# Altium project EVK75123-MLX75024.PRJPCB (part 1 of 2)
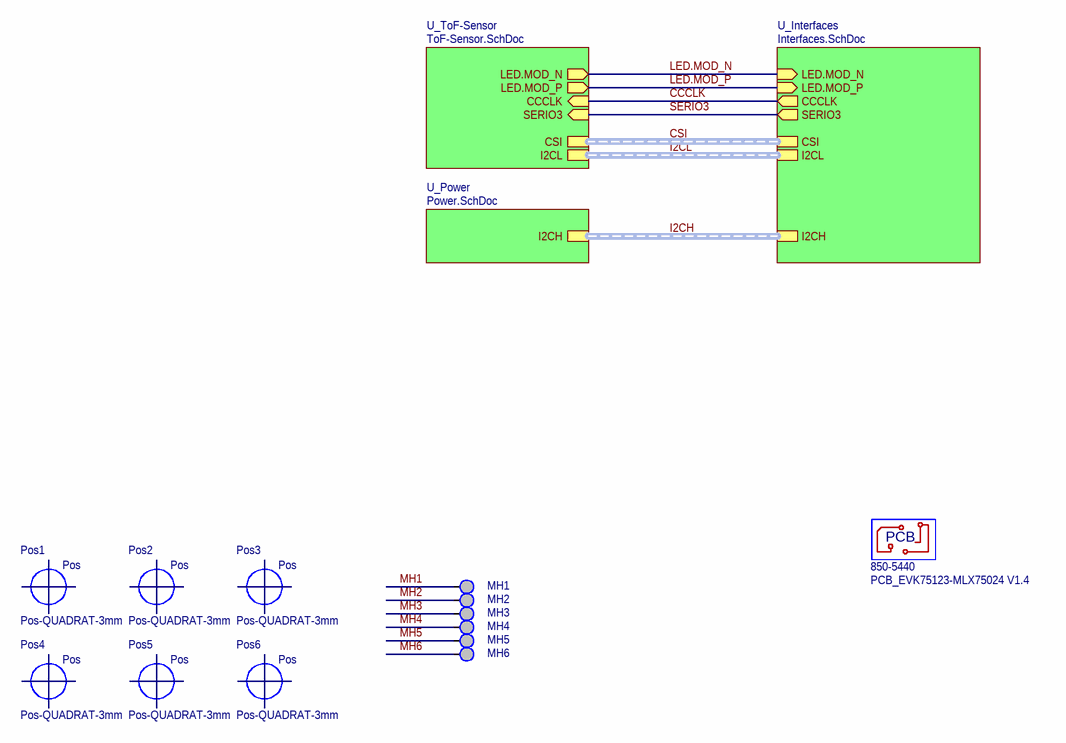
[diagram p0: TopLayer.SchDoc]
prj_vers: V1.4; prj_num: PN2017002.13; prj_name: EVK75123-MLX75024
4 sheets, 222 parts. Net scope: hierarchical (ports join the sheet entries above them; power ports are global).
Board file: EVK75123-MLX75024.PcbDoc
Sheets:
  TopLayer.SchDoc
    U_Power = Power.SchDoc
    U_ToF-Sensor = ToF-Sensor.SchDoc
    U_Interfaces = Interfaces.SchDoc

## Sheet TopLayer.SchDoc: Top Layer
size A4; CheckedBy: ROB; Author: Vorname Nachname; DrawnBy: DST; Organization: BECOM BLUETECHNIX; Address1: Gutheil-Schoder-Gasse 17; Address2: A - 1230 Wien; Address3: AUSTRIA; DocumentNumber: 1; Revision: V1.0; SheetNumber: 1; SheetTotal: 4; PageSetup: Record=PageOptions¦CenterHorizontal=True¦CenterVertical=True¦PrintScale=1.00¦XCorrection=1.00¦YCorrection=1.00¦PrintKind=0¦BorderSize=5000000¦LeftOffset=0¦BottomOffset=0¦Orientation=2¦PaperLength=1000¦PaperWidth=1000¦Scale=100¦PaperSource=15¦PrintQuality=600¦MediaType=1¦DitherType=10¦PrintScaleMode=1¦PaperKind=A4 (210 x 297 mm)

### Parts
MH1  Test Pad  [PAD_M2-5x5]  (value not drawn)  (no BOM)
MH2  Test Pad  [PAD_M2-5x5]  (value not drawn)  (no BOM)
MH3  Test Pad  [PAD_M2-5x5]  (value not drawn)  (no BOM)
MH4  Test Pad  [PAD_M2-5x5]  (value not drawn)  (no BOM)
MH5  Test Pad  [PAD_M2-5x5]  (value not drawn)  (no BOM)
MH6  Test Pad  [PAD_M2-5x5]  (value not drawn)  (no BOM)
PCB  850-5440  [PCB]
Pos1  Position  [Pos-QUADRAT]  (value not drawn)
Pos2  Position  [Pos-QUADRAT]  (value not drawn)
Pos3  Position  [Pos-QUADRAT]  (value not drawn)
Pos4  Position  [Pos-QUADRAT]  (value not drawn)
Pos5  Position  [Pos-QUADRAT]  (value not drawn)
Pos6  Position  [Pos-QUADRAT]  (value not drawn)

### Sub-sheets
U_Interfaces = Interfaces.SchDoc: I2CL (harness I2C), CCCLK (out), LED.MOD_N (in), LED.MOD_P (in), CSI (harness CSI), I2CH (harness I2C), SERIO3 (out)
U_Power = Power.SchDoc: I2CH (harness I2C)
U_ToF-Sensor = ToF-Sensor.SchDoc: LED.MOD_N (out), LED.MOD_P (out), CSI (harness CSI), CCCLK (in), I2CL (harness I2C), SERIO3 (in)

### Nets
CCCLK: sheet U_ToF-Sensor/CCCLK, sheet U_Interfaces/CCCLK
LED.MOD_N: sheet U_ToF-Sensor/LED.MOD_N, sheet U_Interfaces/LED.MOD_N
LED.MOD_P: sheet U_ToF-Sensor/LED.MOD_P, sheet U_Interfaces/LED.MOD_P
MH1: MH1.1
MH2: MH2.1
MH3: MH3.1
MH4: MH4.1
MH5: MH5.1
MH6: MH6.1
SERIO3: sheet U_ToF-Sensor/SERIO3, sheet U_Interfaces/SERIO3

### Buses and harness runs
harness CSI = sheet U_Interfaces/CSI = sheet U_ToF-Sensor/CSI
harness I2CH = sheet U_Interfaces/I2CH = sheet U_Power/I2CH
harness I2CL = sheet U_Interfaces/I2CL = sheet U_ToF-Sensor/I2CL

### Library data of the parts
MH1-MH6 = d95d2f47-965b-47b2-ac00-e8d5b9325de3: M2 Mounting Hole 5x5; Manufacturer: Bluetechnix; ArticleNumber: 810-0545; Inventory Storage Name: L2; Sachgruppe: SV_TEST; IsReviewed: 1; Typ: Mount Hole
PCB = aa2248c4-82a7-44fd-bdc5-6c4486715852: PCB_EVK75123-MLX75024 V1.4; Manufacturer: Bluetechnix; Inventory Storage Name: L2; Sachgruppe: PCB_EXTPROJEKT; SachgruppeCode: externe Projekte; IsReviewed: 0; Kunde: Melexis
Pos1-Pos6 = A97550DC-E5EA-465D-9168-34E3565B8720: Pos-QUADRAT-3mm; Manufacturer: Bluetechnix; MountOption: DNP; ArticleNumber: 880-0007; Inventory Storage Name: L2; Sachgruppe: DIV_SYMBOLE; SachgruppeCode: PCB-Symbole; IsReviewed: 1; Groesse: 3mm

## Sheet Power.SchDoc: Power Supplies
size A4; CheckedBy: ROB; Author: Vorname Nachname; DrawnBy: DST; Organization: BECOM BLUETECHNIX; Address1: Gutheil-Schoder-Gasse 17; Address2: A - 1230 Wien; Address3: AUSTRIA; DocumentNumber: 4; Revision: V1.0; SheetNumber: 4; SheetTotal: 4
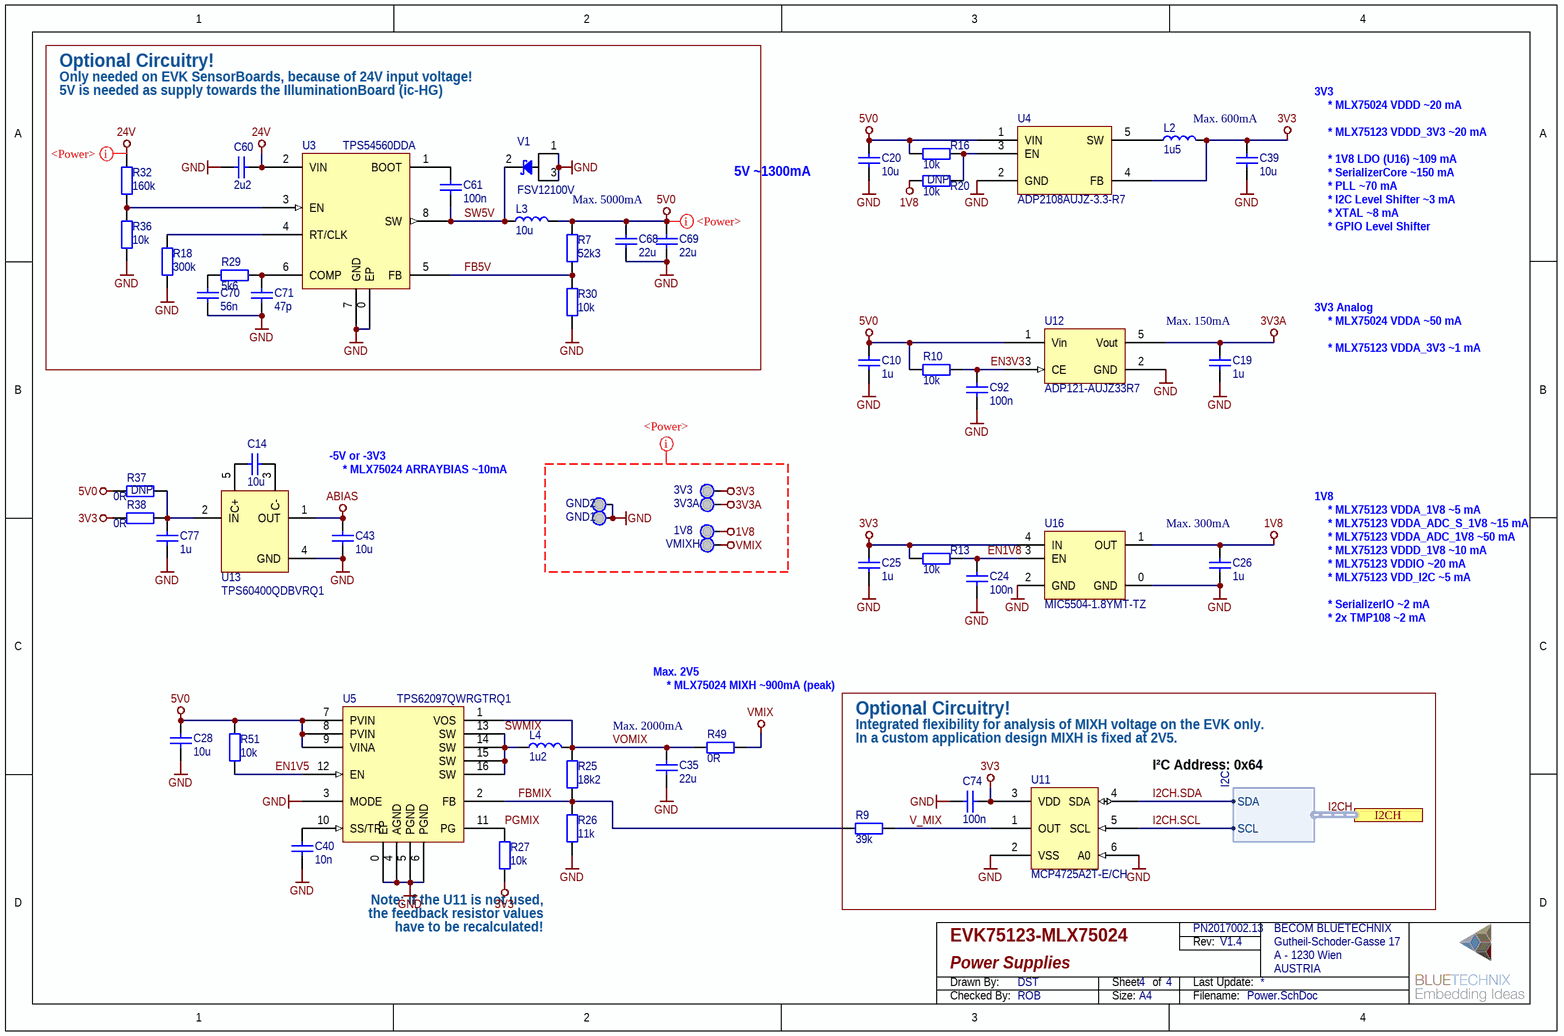
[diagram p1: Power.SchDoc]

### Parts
1V8  Test Pad  [PAD_1.27mm_HMD]  (value not drawn)  (no BOM)
3V3  Test Pad  [PAD_1.27mm_HMD]  (value not drawn)  (no BOM)
3V3A  Test Pad  [PAD_1.27mm_HMD]  (value not drawn)  (no BOM)
C10  C: 1u  [0805]  (hidden comment: Capacitor non-polarized)
C14  C: 10u  [0805]  (hidden comment: Capacitor non-polarized)
C19  C: 1u  [0805]  (hidden comment: Capacitor non-polarized)
C20  C: 10u  [0805]  (hidden comment: Capacitor non-polarized)
C24  C: 100n  [0402]  (hidden comment: Capacitor non-polarized)
C25  C: 1u  [0805]  (hidden comment: Capacitor non-polarized)
C26  C: 1u  [0805]  (hidden comment: Capacitor non-polarized)
C28  C: 10u  [0805]  (hidden comment: Capacitor non-polarized)
C35  C: 22u  [1206]  (hidden comment: Capacitor non-polarized)
C39  C: 10u  [0805]  (hidden comment: Capacitor non-polarized)
C40  C: 10n  [0402]  (hidden comment: Capacitor non-polarized)
C43  C: 10u  [0805]  (hidden comment: Capacitor non-polarized)
C60  C: 2u2  [1210]  (hidden comment: Capacitor non-polarized)
C61  C: 100n  [0402]  (hidden comment: Capacitor non-polarized)
C68  C: 22u  [1206]  (hidden comment: Capacitor non-polarized)
C69  C: 22u  [1206]  (hidden comment: Capacitor non-polarized)
C70  C: 56n  [0402]  (hidden comment: Capacitor non-polarized)
C71  C: 47p  [0402]  (hidden comment: Capacitor non-polarized)
C74  C: 100n  [0402]  (hidden comment: Capacitor non-polarized)
C77  C: 1u  [0805]  (hidden comment: Capacitor non-polarized)
C92  C: 100n  [0402]  (hidden comment: Capacitor non-polarized)
GND1  Test Pad  [PAD_1.27mm_HMD]  (value not drawn)  (no BOM)
GND2  Test Pad  [PAD_1.27mm_HMD]  (value not drawn)  (no BOM)
L2  L: 1u5  [WE-TPC_S]  (hidden comment: Inductor)
L3  L: 10u  [CC-XAL5050]  (hidden comment: Inductor)
L4  L: 1u2  [WE-TPC_MH]  (hidden comment: Inductor)
R7  R: 52k3  [0402]  (hidden comment: Resistor)
R9  R: 39k  [0402]  (hidden comment: Resistor)
R10  R: 10k  [0402]  (hidden comment: Resistor)
R13  R: 10k  [0402]  (hidden comment: Resistor)
R16  R: 10k  [0402]  (hidden comment: Resistor)
R18  R: 300k  [0402]  (hidden comment: Resistor)
R20  R: 10k  MountOption: DNP  [0402]  (hidden comment: Resistor)
R25  R: 18k2  [0402]  (hidden comment: Resistor)
R26  R: 11k  [0402]  (hidden comment: Resistor)
R27  R: 10k  [0402]  (hidden comment: Resistor)
R29  R: 5k6  [0402]  (hidden comment: Resistor)
R30  R: 10k  [0402]  (hidden comment: Resistor)
R32  R: 160k  [0402]  (hidden comment: Resistor)
R36  R: 10k  [0402]  (hidden comment: Resistor)
R37  R: 0R  MountOption: DNP  [0805]  (hidden comment: Resistor)
R38  R: 0R  [0805]  (hidden comment: Resistor)
R49  R: 0R  [0805]  (hidden comment: Resistor)
R51  R: 10k  [0402]  (hidden comment: Resistor)
U3  NAME: TPS54560DDA  [PSO8-1.27-7.3]  (hidden comment: TPS54061)
U4  NAME: ADP2108AUJZ-3.3-R7  [TSOT23-5-0.95-2.8]  (hidden comment: ADP2108TSOP)
U5  NAME: TPS62097QWRGTRQ1  [VQFN16A4-0.5-3-1]  (hidden comment: TPS62097)
U11  NAME: MCP4725A2T-E/CH  [SOT23-6-0.95--3.3]  (hidden comment: MCP4725)
U12  NAME: ADP121-AUJZ33R7  [SOT23-5-0.95--3.6]  (hidden comment: High-Speed LDO Voltage-Regulator)
U13  NAME: TPS60400QDBVRQ1  [SOT23-5-0.95--3.6]  (hidden comment: MAX828)
U16  NAME: MIC5504-1.8YMT-TZ  [DFN4-0.65-1-0.5]  (hidden comment: MIC550x)
V1  NAME: FSV12100V  [TO-277-3]  (hidden comment: Default Diode)
VMIXH  Test Pad  [PAD_1.27mm_HMD]  (value not drawn)  (no BOM)

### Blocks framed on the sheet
Optional Circuitry!: C60 C61 C68-C71 L3 R7 R18 R29 R30 R32 R36 U3 V1
Optional Circuitry!: C74 R9 U11

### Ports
I2CH (harness I2C)

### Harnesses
I2C: SCL, SDA

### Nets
1V8: 1V8.1 C26.2 R20.1 U16.1(OUT)
3V3: 3V3.1 C25.2 C39.2 C74.2 L2.2 R13.1 R27.2 R38.2 U4.4(FB) U11.3(VDD) U16.4(IN)
3V3A: 3V3A.1 C19.2 U12.5(Vout)
5V0: C10.2 C20.2 C28.2 C68.2 C69.2 L3.2 R7.2 R10.1 R16.1 R37.2 R51.2 U4.1(VIN) U5.7(PVIN) U5.8(PVIN) U5.9(VINA) U12.1(Vin)
24V: C60.2 R32.2 U3.2(VIN)
ABIAS: C43.1 U13.1(OUT)
GND: C10.1 C19.1 C20.1 C24.2 C25.1 C26.1 C28.1 C35.1 C39.1 C40.1 C43.2 C60.1 C68.1 C69.1 C70.1 C71.1 C74.1 C77.1 C92.2 GND1.1 GND2.1 R18.1 R26.1 R30.2 R36.2 U3.0(EP) U3.7(GND) U4.2(GND) U5.0(EP) U5.3(MODE) U5.4(AGND) U5.5(PGND) U5.6(PGND) U11.2(VSS) U11.6(A0) U12.2(GND) U13.4(GND) U16.0(GND) U16.2(GND) V1.1(A) V1.3(A)
VMIX: R49.1 VMIXH.1
EN1V5: R51.1 U5.12(EN)
EN1V8: C24.1 R13.2 U16.3(EN)
EN3V3: C92.1 R10.2 U12.3(CE)
FB5V: R7.1 R30.1 U3.5(FB)
FBMIX: R9.1 R25.1 R26.2 U5.2(FB)
I2CH.SCL: U11.5(SCL) ; port I2CH.SCL
I2CH.SDA: U11.4(SDA) ; port I2CH.SDA
PGMIX: R27.1 U5.11(PG)
SW5V: C61.2 L3.1 U3.8(SW) V1.2(K)
SWMIX: L4.1 U5.13(SW) U5.14(SW) U5.15(SW) U5.16(SW)
V_MIX: R9.2 U11.1(OUT)
VOMIX: C35.2 L4.2 R25.2 R49.2 U5.1(VOS)
NetC14_1: C14.1 U13.3(C-)
NetC14_2: C14.2 U13.5(C+)
NetC40_2: C40.2 U5.10(SS/TR)
NetC61_1: C61.1 U3.1(BOOT)
NetC70_2: C70.2 R29.2
NetC71_2: C71.2 R29.1 U3.6(COMP)
NetC77_2: C77.2 R37.1 R38.1 U13.2(IN)
NetL2_1: L2.1 U4.5(SW)
NetR16_2: R16.2 R20.2 U4.3(EN)
NetR18_2: R18.2 U3.4(RT/CLK)
NetR32_1: R32.1 R36.1 U3.3(EN)

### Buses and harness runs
harness I2CH = port I2CH

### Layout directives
net class <Power>: 1V8, 3V3, 3V3A, 5V0, 24V, GND, VMIX

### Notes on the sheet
- Only needed on EVK SensorBoards, because of 24V input voltage!
- 5V is needed as supply towards the IlluminationBoard (ic-HG)
- 3V3
- * MLX75024 VDDD |0 mA
- 5V
  300mA
- (near L2) Max. 600mA
- * 1V8 LDO (U16)
  09 mA
- * MLX75123 VDDD_3V3 |0 mA
- * SerializerCore
  50 mA
- Max. 5000mA
- * PLL ~70 mA
- * I2C Level Shifter ~3 mA
- * XTAL ~8 mA
- * GPIO Level Shifter
- 3V3 Analog
- Max. 150mA
- * MLX75024 VDDA ~50 mA
- * MLX75123 VDDA_3V3
  mA
- -5V or -3V3
- * MLX75024 ARRAYBIAS
  0mA
- 1V8
- * MLX75123 VDDA_1V8 ~5 mA
- Max. 300mA
- * MLX75123 VDDA_ADC_S_1V8
  5 mA
- * MLX75123 VDDA_ADC_1V8 ~50 mA
- * MLX75123 VDDD_1V8
  0 mA
- * MLX75123 VDDIO |0 mA
- * MLX75123 VDD_I2C ~5 mA
- * SerializerIO | mA
- * 2x TMP108 | mA
- Max. 2V5
- * MLX75024 MIXH ~900mA (peak)
- Max. 2000mA
- Integrated flexibility for analysis of MIXH voltage on the EVK only.
- In a custom application design MIXH is fixed at 2V5.
- (near U11) I²C Address: 0x64
- Note: If the U11 is not used,
- the feedback resistor values
- have to be recalculated!

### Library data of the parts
1V8 3V3 3V3A GND1 GND2 VMIXH = 27F6ED3A-68E1-4461-ACCB-196987D0D511: Test Pad 1.27mm; Manufacturer: Bluetechnix; ArticleNumber: 810-0043; Inventory Storage Name: L2; Sachgruppe: SV_TEST; IsReviewed: 1
C10 C19 C25 C26 C77 = 81c3c59d-90b6-45b0-bf00-0272af6cd427: C-0805-1u-16V-10%; Manufacturer: KEMET; ArticleNumber: 710-0292; NAME: C0805C105K4RACTU; Inventory Storage Name: LBaut; Inventory Storage Section: C6; Sachgruppe: C_KERAMIK; SachgruppeCode: Keramikscheiben; IsReviewed: 1; InternalPrice: 0,037954; InternalStock: 308; U: 16V; Toleranz: 10%; Dielektrikum: X7R; T_Koeffizient: ±10%; T-bereich: -55°C : +125°C; Montage: SMD
C14 C20 C28 C39 C43 = cf916b3d-c256-4339-9e5e-93049cd4a086: C-0805-10u-6.3V-10%; Manufacturer: AVX; ArticleNumber: 710-0369; NAME: 08056C106KAT2A; Inventory Storage Name: LBaut; Sachgruppe: C_KERAMIK; SachgruppeCode: Keramikscheiben; IsReviewed: 1; InternalPrice: 0,227407; InternalStock: 48; U: 6.3V; Toleranz: 10%; Dielektrikum: X7R; T_Koeffizient: ±15%; T-bereich: -55°C : +125°C; Montage: SMD; Inventory Storage Section: C7
C24 C92 = 54C877D5-E705-4C14-AD3D-8F4F7B57D597: C-0402-100n-16V-10%; Manufacturer: Murata; ArticleNumber: 710-0138; NAME: GRM155R71C104KA88D; Inventory Storage Name: LBaut; Inventory Storage Section: C3; Sachgruppe: C_KERAMIK; SachgruppeCode: Keramikscheiben; IsReviewed: 1; U: 16V; Toleranz: 10%; Dielektrikum: X7R; T_Koeffizient: ± 15%; T-bereich: -55°C : +125°C; Montage: SMD; InternalPrice: 0.011327; InternalStock: 597514
C35 C68 C69 = f3686e78-9391-4e70-aeac-48820653bfbe: C-1206-22u-16V-10%-X6S; Manufacturer: Murata; ArticleNumber: 710-0343; NAME: GRM31CC81C226ME15L; Inventory Storage Name: LBaut; Sachgruppe: C_KERAMIK; SachgruppeCode: Keramikscheiben; IsReviewed: 1; InternalPrice: 0,277045; InternalStock: 60; U: 16V; Toleranz: 20%; Dielektrikum: X6S; T_Koeffizient: ± 15%; T-bereich: -55°C : +105°C; Montage: SMD; Inventory Storage Section: C7
C40 = F3AE35C4-38BD-40F1-9F89-DFB06C81C85C: C-0402-10n-25V-10%; Manufacturer: Murata; ArticleNumber: 710-0222; NAME: GRM155R71E103KA01D; Inventory Storage Name: LBaut; Inventory Storage Section: C5; Sachgruppe: C_KERAMIK; SachgruppeCode: Keramikscheiben; IsReviewed: 1; InternalPrice: 0,008319; InternalStock: 2134; U: 25V; Toleranz: 10%; Dielektrikum: X7R; T_Koeffizient: ± 15%; T-bereich: -55°C : +125°C; Montage: SMD
C60 = c11633e3-883f-4ea1-bab5-305a930c1712: C-1210-2u2-100V-X7R; Manufacturer: Kemet; ArticleNumber: 710-0311; NAME: C1210C225K1RACTU; Inventory Storage Name: LBaut; Inventory Storage Section: C6; Sachgruppe: C_KERAMIK; SachgruppeCode: Keramikscheiben; IsReviewed: 1; InternalPrice: 0,222241; U: 100V; Toleranz: 10%; Dielektrikum: X7R; T_Koeffizient: ± 15%; T-bereich: -55°C : +125°C; Montage: SMD; InternalStock: 196
C61 = 54C877D5-E705-4C14-AD3D-8F4F7B57D597: C-0402-100n-16V-10%; manufacturer: Murata; ArticleNumber: 710-0138; Inventory Storage Name: LBaut; Inventory Storage Section: C3; IsReviewed: 1; NAME: GRM155R71C104KA88D; Sachgruppe: C_KERAMIK; SachgruppeCode: Keramikscheiben; Dielektrikum: X7R; Montage: SMD; T-bereich: -55°C : +125°C; T_Koeffizient: ± 15%; Toleranz: 10%; U: 16V; InternalPrice: 0,009756; InternalStock: 539102
C70 = 1E20E73B-F110-4E82-8339-165F61C8EA2C: C-0402-56n-16V-10%; Manufacturer: KEMET; ArticleNumber: 710-0017; NAME: C0402C563K4RACTU; Inventory Storage Name: LBaut; Inventory Storage Section: C1; Sachgruppe: C_KERAMIK; SachgruppeCode: Keramikscheiben; IsReviewed: 1; InternalPrice: 0,049062; U: 16V; Toleranz: 10%; Dielektrikum: X7R; T_Koeffizient: ±15%; T-bereich: -55°C : +125°C; Montage: SMD; InternalStock: 10
C71 = D729ACC2-10DA-4FA5-B88D-D769CEA10CA7: C-0402-47p-50V-5%; Manufacturer: AVX; ArticleNumber: 710-0210; NAME: 04025A470JAT2A; Inventory Storage Name: LBaut; Inventory Storage Section: C5; Sachgruppe: C_KERAMIK; SachgruppeCode: Keramikscheiben; IsReviewed: 1; InternalPrice: 0,052294; InternalStock: 222; U: 50V; Toleranz: 5%; Dielektrikum: C0G; T_Koeffizient: ± 30ppm/°C; T-bereich: -55°C : +125°C; Montage: SMD
C74 = 54C877D5-E705-4C14-AD3D-8F4F7B57D597: C-0402-100n-16V-10%; Manufacturer: Murata; ArticleNumber: 710-0138; NAME: GRM155R71C104KA88D; Inventory Storage Name: LBaut; Inventory Storage Section: C3; Sachgruppe: C_KERAMIK; SachgruppeCode: Keramikscheiben; IsReviewed: 1; Dielektrikum: X7R; Montage: SMD; T-bereich: -55°C : +125°C; T_Koeffizient: ± 15%; Toleranz: 10%; U: 16V; InternalPrice: 0,009756; InternalStock: 539102
L2 = AA01E2E0-360B-48B6-A8ED-1CE20DAAC179: L-WE-TPC-S-1u5-1.75A-30%; Manufacturer: Würth Elektronik; ArticleNumber: 770-0019; NAME: 744031001; Inventory Storage Name: LBaut; Inventory Storage Section: I2; Sachgruppe: IN_SPEICHERDROSSELN; SachgruppeCode: Speicherdrosseln; IsReviewed: 1; Core: Ferrit; I: 1.75A; I_sat: 1.55A; Toleranz: 30%; R_dc: 40mR; f_res: 125MHz; Schirm: y; Bauform: TPC-S 3817; Montage: SMD; T-bereich: -40°C : +125°C; InternalPrice: 0,330529; InternalStock: 980
L3 = ebdded0c-8af9-41bf-8a12-8fcfe7c8f423: L-XAL5050-10u-4.9A-20%; Manufacturer: Coilcraft; ArticleNumber: 770-0186; NAME: XAL5050-103MEB; Inventory Storage Name: LBaut; Inventory Storage Section: I16; Sachgruppe: IN_SPEICHERDROSSELN; SachgruppeCode: Speicherdrosseln; IsReviewed: 1; InternalPrice: 2,174523; InternalStock: 54; Core: Composite; I: 4.9A; Toleranz: 20%; R_dc: 40.9mR; f_res: 15MHz; Schirm: y; Montage: SMD; T-bereich: -40°C : +125°C
L4 = 8BFA9BBF-0541-4A3A-9EC6-D13966CA382E: L-WE-TPC-MH-1u2-3.1A; Manufacturer: Würth Elektronik; ArticleNumber: 770-0095; NAME: 7440430012; Inventory Storage Name: LBaut; Inventory Storage Section: I8; Sachgruppe: IN_SPEICHERDROSSELN; SachgruppeCode: Speicherdrosseln; IsReviewed: 1; InternalPrice: 0,830769; InternalStock: 90; Core: NiZn; I: 3.1A; I_sat: 2.8A; Toleranz: 30%; R_dc: 17mR; f_res: 150MHz; Schirm: y; Bauform: TPC-MH 4828; Montage: SMD; T-bereich: -40°C : +125°C
R7 = 07979F3D-4677-465C-93AF-4C0DB5A9740C: R-0402-52k3-1%; Manufacturer: Multicomp; ArticleNumber: 780-0113; NAME: MC 0.0625W 0402 1% 52K3; Inventory Storage Name: LBaut; Inventory Storage Section: R3; Sachgruppe: R_DICKSCHICHT; SachgruppeCode: Dickschicht; IsReviewed: 1; InternalPrice: 0,022692; InternalStock: 1828; P: 0.0625W; Toleranz: 1%; T_Koeffizient: ± 100ppm/°C; Montage: SMD; T-bereich: -55°C : +155°C
R9 = 67127F43-32FE-42C1-8D78-F67E7CEF1B7C: R-0402-39k-1%; Manufacturer: YAGEO; ArticleNumber: 780-0394; NAME: RC0402FR-0739KL; Inventory Storage Name: LBaut; Inventory Storage Section: R8; Sachgruppe: R_DICKSCHICHT; SachgruppeCode: Dickschicht; IsReviewed: 1; InternalPrice: 0,002427; InternalStock: 16956; P: 0.063W; Toleranz: 1%; T_Koeffizient: ± 250ppm/°C; Montage: SMD; T-bereich: -55°C : +155°C
R10 R13 R16 R20 R27 R51 = BCCEBF77-39D2-4523-BB97-913D11062098: R-0402-10k-1%; Manufacturer: YAGEO; ArticleNumber: 780-0217; NAME: RC0402FR-0710KL; Inventory Storage Name: LBaut; Inventory Storage Section: R5; Sachgruppe: R_DICKSCHICHT; SachgruppeCode: Dickschicht; IsReviewed: 1; P: 0.063W; Toleranz: 1%; T_Koeffizient: ± 250ppm/°C; Montage: SMD; T-bereich: -55°C : +155°C; InternalPrice: 0,028158; InternalStock: 1616
R18 = 36816F37-1497-45EC-A648-00BA6DD1BED6: R-0402-300k-1%; Manufacturer: PhyComp; ArticleNumber: 780-0002; NAME: RC0402FR-07300KL; Inventory Storage Name: LBaut; Inventory Storage Section: R1; Sachgruppe: R_DICKSCHICHT; SachgruppeCode: Dickschicht; IsReviewed: 1; InternalPrice: 0,005666; InternalStock: 780; P: 0.063W; Toleranz: 1%; T_Koeffizient: ± 100ppm/°C; Montage: SMD
R25 = 0f3e9f1d-d298-49d2-b2be-77c58d20251a: R-0402-18k2-1%; Manufacturer: Multicomp; ArticleNumber: 780-0578; NAME: MCMR04X1822FTL; Inventory Storage Name: LBaut; Inventory Storage Section: R11; Sachgruppe: R_DICKSCHICHT; SachgruppeCode: Dickschicht; IsReviewed: 1; InternalPrice: 0; InternalStock: 56; P: 0.0625W; Toleranz: 1%; T_Koeffizient: ± 250ppm/°C; Montage: SMD; T-bereich: -55°C : +155°C
R26 = 76176D2D-1863-4245-B5AD-CF9DCC6B9442: R-0402-11k-1%; Manufacturer: Vishay; ArticleNumber: 780-0321; NAME: CRCW040211K0FKED; Inventory Storage Name: LBaut; Inventory Storage Section: R7; Sachgruppe: R_DICKSCHICHT; SachgruppeCode: Dickschicht; IsReviewed: 1; InternalPrice: 0,016666; InternalStock: 870; P: 0.063W; Toleranz: 1%; T_Koeffizient: ± 100ppm/°C; Montage: SMD
R29 = 83EC2591-E07F-42F5-A99F-8FBBFCE4BDFC: R-0402-5k6-5%; Manufacturer: YAGEO; ArticleNumber: 780-0215; NAME: RC0402JR-075K6L; Inventory Storage Name: LBaut; Inventory Storage Section: R5; Sachgruppe: R_DICKSCHICHT; SachgruppeCode: Dickschicht; IsReviewed: 1; InternalPrice: 0,00795; InternalStock: 952; P: 0.063W; Toleranz: 5%; T_Koeffizient: ± 200ppm/°C; Montage: SMD; T-bereich: -55°C : +150°C
R30 R36 = BCCEBF77-39D2-4523-BB97-913D11062098: R-0402-10k-1%; manufacturer: YAGEO; ArticleNumber: 780-0217; Inventory Storage Name: LBaut; Inventory Storage Section: R5; NAME: RC0402FR-0710KL; Sachgruppe: R_DICKSCHICHT; SachgruppeCode: Dickschicht; Montage: SMD; P: 0.063W; T_Koeffizient: ± 250ppm/°C; Toleranz: 1%; IsReviewed: 1; T-bereich: -55°C : +155°C; InternalPrice: 0,028158; InternalStock: 1616
R32 = 3de2694c-57ce-4287-83c5-ae949e3a1a26: R-0402-160k-1%; Manufacturer: VISHAY DRALORIC; ArticleNumber: 780-0523; NAME: CRCW0402160KFKED; Inventory Storage Name: LBaut; Sachgruppe: R_DICKSCHICHT; SachgruppeCode: Dickschicht; IsReviewed: 1; InternalPrice: 0,021111; InternalStock: 862; P: 0.063W; Toleranz: 1%; T_Koeffizient: ± 100ppm/°C; Montage: SMD; T-bereich: -55°C : +155°C
R37 R38 R49 = 96878DCE-2E24-48BD-A958-A9B2669E8EA5: R-0805-0R-5%; Manufacturer: YAGEO; ArticleNumber: 780-0259; NAME: RC0805JR-070RL; Inventory Storage Name: LBaut; Inventory Storage Section: R6; Sachgruppe: R_DICKSCHICHT; SachgruppeCode: Dickschicht; IsReviewed: 1; InternalPrice: 0,001333; InternalStock: 7272; P: 0.125W; Toleranz: 5%; T_Koeffizient: ± 250ppm/°C; Montage: SMD
U3 = 83e8cd34-1e26-4937-9357-3a852f02699a: 4.5 V to 60 V Input, 5 A, Step Down DC-DC Converter with Eco-mode; Manufacturer: Texas Instruments; ArticleNumber: 700-1098; Inventory Storage Name: LBaut; Sachgruppe: PM_BUCK; SachgruppeCode: Buck; IsReviewed: 1; U_in(max): 60V; U_in(min): 4.5V; U_out(max): 58.8V; U_out(min): 0.8V; fix_var: var; I_out: 5A; T-bereich: -40°C : +150°C; Bauform: HSOP8; Montage: SMD; Frequenz: 100kHz : 2.5MHz; InternalPrice: 3,659642; InternalStock: 8; Inventory Storage Section: U48
U4 = 1d5217f7-f1b1-4eac-83a6-f563bfe7f909: 3.3V Fixed, 600 mA, 3 MHz, Step-Down DC-to-DC Converter; Manufacturer: Analog Devices; ArticleNumber: 700-0890; Inventory Storage Name: LBaut; Inventory Storage Section: U34; Sachgruppe: PM_BUCK; SachgruppeCode: Buck; IsReviewed: 1; InternalPrice: 0,57125; InternalStock: 108; U_in(max): 5.5V; U_in(min): Vout; U_out(max): 3.38V; U_out(min): 3.22V; I_out: 600mA; T-bereich: -40°C : +125°C; Bauform: SOT-23-5; Montage: SMD; topmark: LAH; Frequenz: 3MHz
U5 = d6bf69c1-61e1-4892-bc66-3b908696a342: High Efficiency single inductor buck/boost 2A; Manufacturer: Texas Instruments; ArticleNumber: 700-1162; Inventory Storage Name: L2; Sachgruppe: PM_BUCK; SachgruppeCode: Buck; IsReviewed: 0; U_in(max): 6V; U_in(min): 2.5V; U_out(min): 0.8V; fix_var: var; T-bereich: -40°C : 125°C; Bauform: VQFN16; Montage: SMD; Frequenz: 1.5MHz : 2.5 MHz
U11 = CE87B2AE-2F79-437B-9DBA-CA9484908A67: 12-Bit Digital-to-Analog Converter with EEPROM Memory; Manufacturer: Microchip; ArticleNumber: 700-0543; Inventory Storage Name: LBaut; Inventory Storage Section: U17; Sachgruppe: IC_DATEN_SIGNALWANDLER; SachgruppeCode: Daten-/Signalwandler; IsReviewed: 1; InternalPrice: 0,710731; InternalStock: 38; Typ: DAC; Inputs: 0; Interface: I²C; U_IO: 2.7V : 5.5V; Aufloesung: 12bit; f_abtast: 166kHz; T-bereich: -40°C : +125°C; Bauform: SOT23-6; Montage: SMD; topmark: AQNN
U12 = 000e727f-cc4e-40e8-9f49-f72307949e4f: 3.3V Fixed, 150 mA, Low Quiescent Current, CMOS Linear Regulator; Manufacturer: Analog Devices; ArticleNumber: 700-0903; Inventory Storage Name: LBaut; Inventory Storage Section: U35; Sachgruppe: PM_LINEAR; IsReviewed: 1; InternalPrice: 0,411864; InternalStock: 80; U_in(max): 5.5V; U_in(min): 2.3V; U_out(min): 1.2V; I_out: 150mA; U_drop_out: 0.12V @ 150mA; T-bereich: -40°C : 125°C; Bauform: TSOT23-5; Montage: SMD; topmark: LA5
U13 = 4dc81be8-c4c1-4461-86d3-06e5047a3865: Switched-Capacitor Voltage Inverters; Manufacturer: TEXAS INSTRUMENTS; ArticleNumber: 700-1163; Inventory Storage Name: L2; Sachgruppe: PM_DIVERSE; SachgruppeCode: Diverse; IsReviewed: 1; U_in(max): 5.5V; U_in(min): 1.8V; U_out(max): -Vin; I_out: 60mA; T-bereich: -40°C : +125°C; Bauform: SOT23-5; Montage: SMD; Kommentar: AEC-Q100; topmark: AWP
U16 = 41ab4844-91b0-416b-8011-5a243bc6cd3e: 1.8V LDO Regulator; Manufacturer: Micrel; ArticleNumber: 700-1161; Inventory Storage Name: L2; Sachgruppe: PM_LINEAR; SachgruppeCode: Linear; IsReviewed: 1; U_in(max): 5.5V; U_in(min): 2.5V; U_out(max): 1.836V; U_out(min): 1.764V; I_out: 300mA; U_drop_out: 160mV @ 300mA; T-bereich: -40°C : +125°C; Bauform: DFN4; Montage: SMD; topmark: WXG
V1 = a2494603-b754-4332-b2d6-676b3f1482f6: 12A, 100V Ultra-Low Vf Schottky Rectifier; Manufacturer: Fairchild; ArticleNumber: 730-0269; Inventory Storage Name: LBaut; Sachgruppe: SE_SCHOTTKY; IsReviewed: 1; U_f: 483mV @ 5A, 25°C; I_f(max): 220A; I_r: 22.5uA; t_rr: 27.33ns; C_@_U_r_f: 1124pF @ 4V, 1MHz; Montage: SMD; T-bereich: -55°C : +150°C; InternalPrice: 0,513508; InternalStock: 60; Inventory Storage Section: V19

## Sheet ToF-Sensor.SchDoc: Sensor / ADC
size A3; CheckedBy: ROB; Author: Vorname Nachname; DrawnBy: DST; Organization: BECOM BLUETECHNIX; Address1: Gutheil-Schoder-Gasse 17; Address2: A - 1230 Wien; Address3: AUSTRIA; DocumentNumber: 3; Revision: V1.0; SheetNumber: 3; SheetTotal: 4; PageSetup: Record=PageOptions¦CenterHorizontal=True¦CenterVertical=True¦PrintScale=0.97¦XCorrection=1.00¦YCorrection=1.00¦PrintKind=0¦BorderSize=5000000¦LeftOffset=0¦BottomOffset=0¦Orientation=2¦PaperLength=1000¦PaperWidth=1000¦Scale=100¦PaperSource=15¦PrintQuality=300¦MediaType=1¦DitherType=10¦PaperKind=A4 (210 x 297 mm)¦PrintScaleMode=1
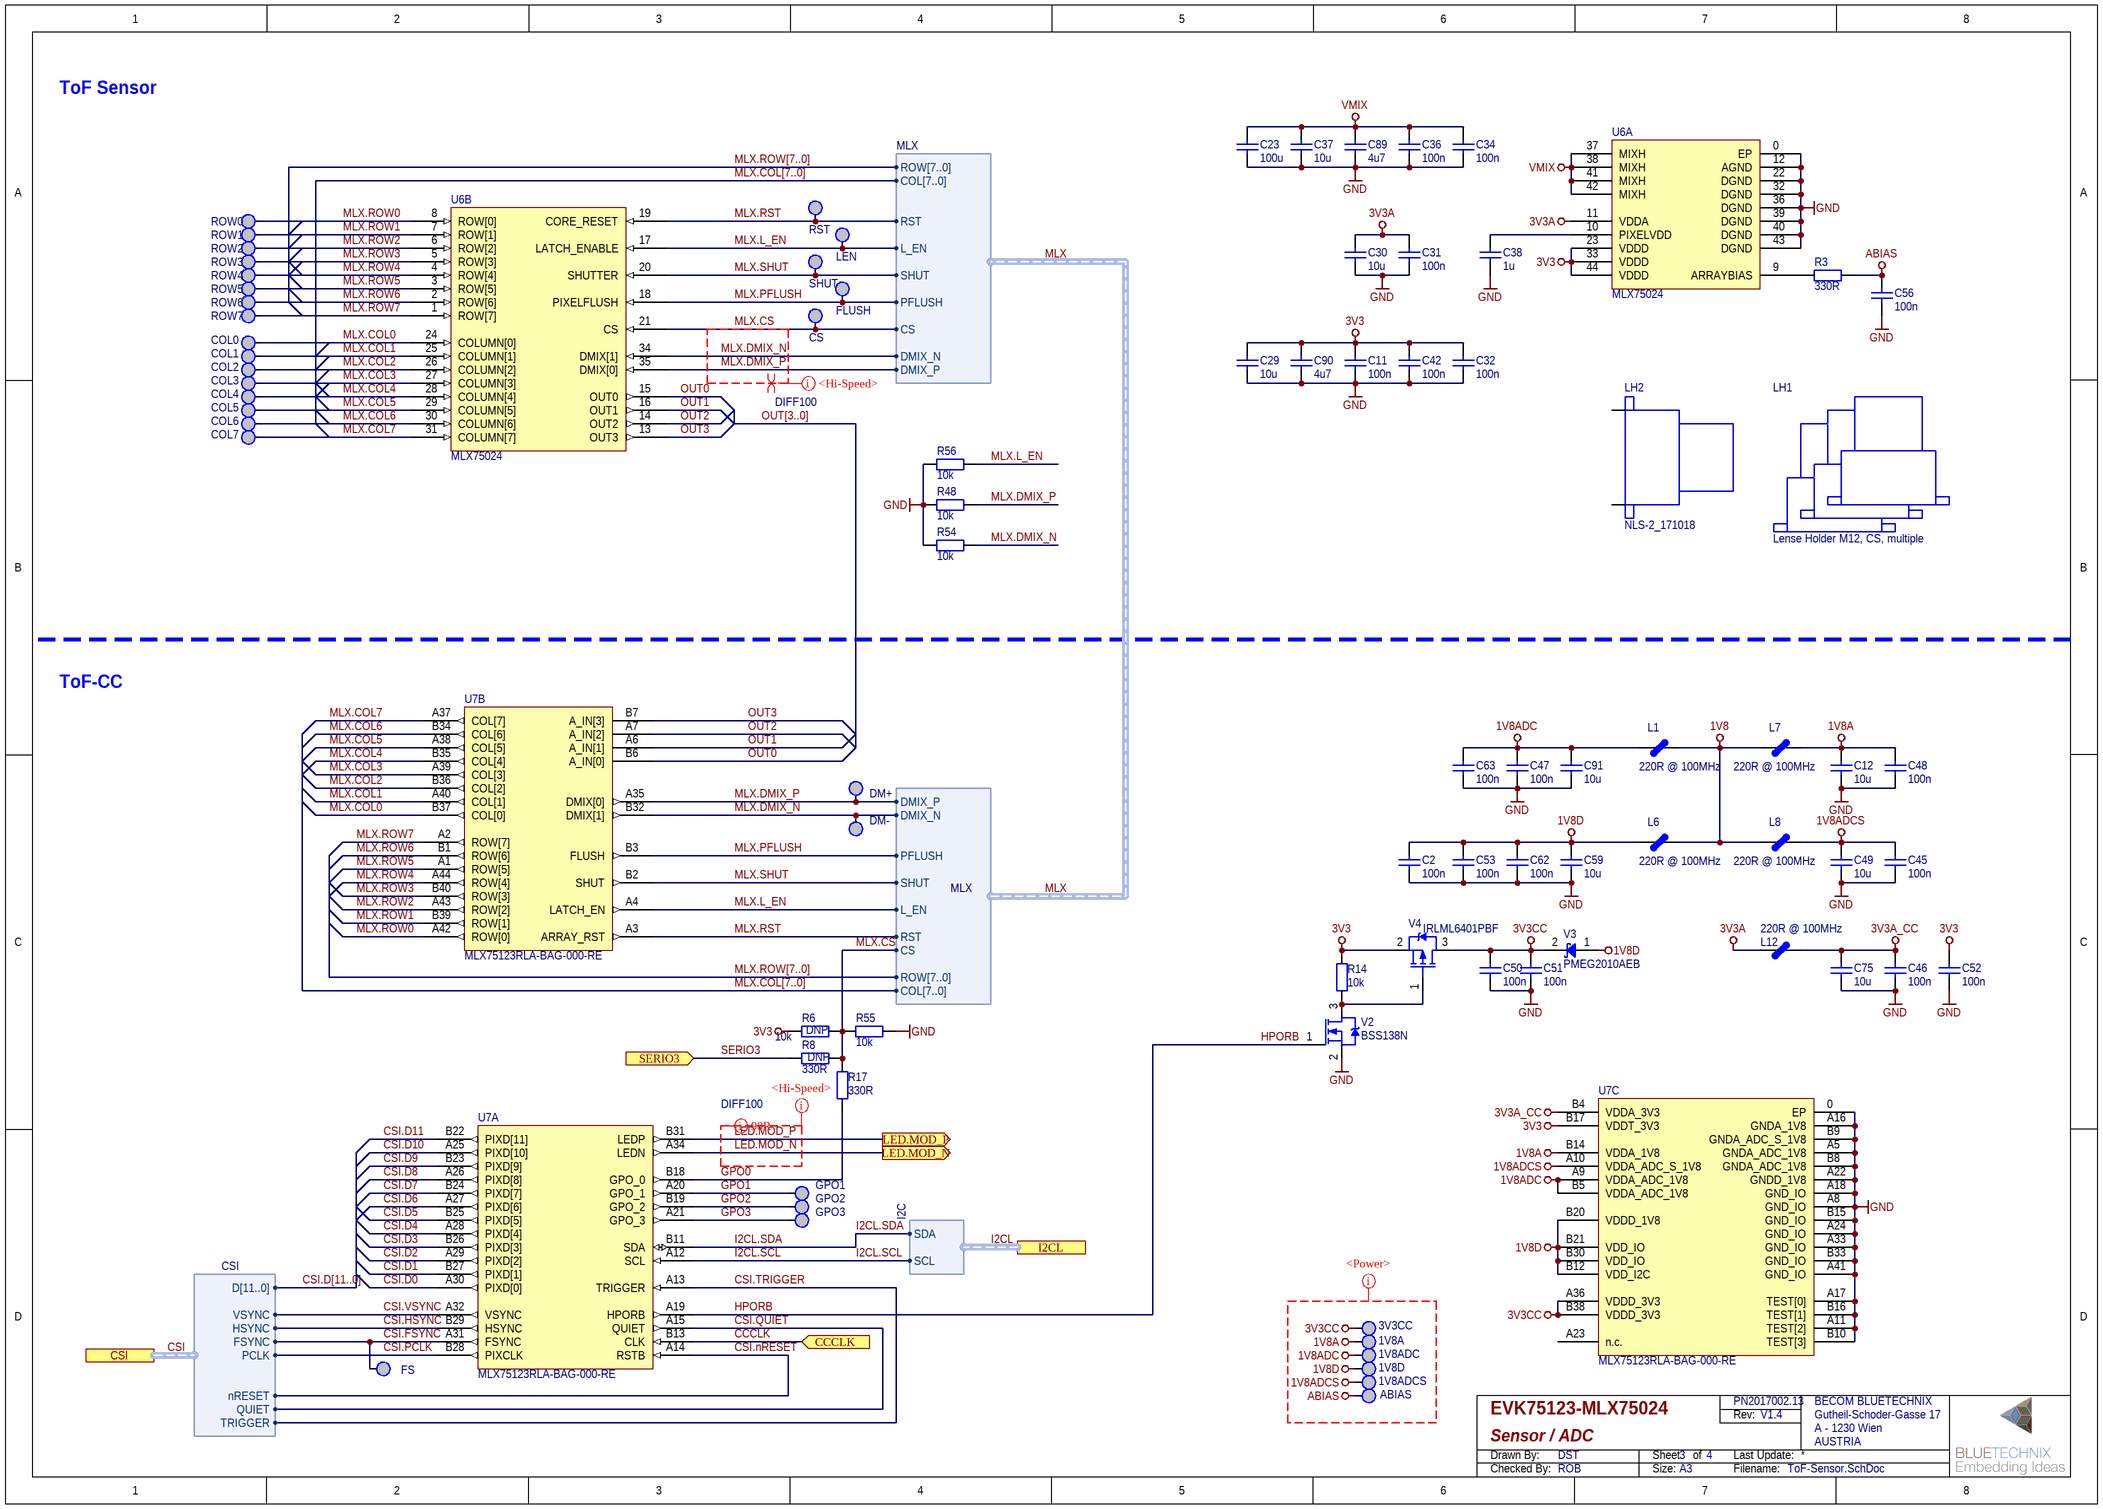
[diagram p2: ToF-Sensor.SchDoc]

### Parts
1V8A  Test Pad  [PAD_1mm_SMD]  (value not drawn)  (no BOM)
1V8ADC  Test Pad  [PAD_1mm_SMD]  (value not drawn)  (no BOM)
1V8ADCS  Test Pad  [PAD_1mm_SMD]  (value not drawn)  (no BOM)
1V8D  Test Pad  [PAD_1mm_SMD]  (value not drawn)  (no BOM)
3V3CC  Test Pad  [PAD_1mm_SMD]  (value not drawn)  (no BOM)
ABIAS  Test Pad  [PAD_1.27mm_HMD]  (value not drawn)  (no BOM)
C2  C: 100n  [0402]  (hidden comment: Capacitor non-polarized)
C11  C: 100n  [0402]  (hidden comment: Capacitor non-polarized)
C12  C: 10u  [0805]  (hidden comment: Capacitor non-polarized)
C23  C: 100u  [1206]  (hidden comment: Capacitor non-polarized)
C29  C: 10u  [0805]  (hidden comment: Capacitor non-polarized)
C30  C: 10u  [0805]  (hidden comment: Capacitor non-polarized)
C31  C: 100n  [0402]  (hidden comment: Capacitor non-polarized)
C32  C: 100n  [0402]  (hidden comment: Capacitor non-polarized)
C34  C: 100n  [0402]  (hidden comment: Capacitor non-polarized)
C36  C: 100n  [0402]  (hidden comment: Capacitor non-polarized)
C37  C: 10u  [0805]  (hidden comment: Capacitor non-polarized)
C38  C: 1u  [0402]  (hidden comment: Capacitor non-polarized)
C42  C: 100n  [0402]  (hidden comment: Capacitor non-polarized)
C45  C: 100n  [0402]  (hidden comment: Capacitor non-polarized)
C46  C: 100n  [0402]  (hidden comment: Capacitor non-polarized)
C47  C: 100n  [0402]  (hidden comment: Capacitor non-polarized)
C48  C: 100n  [0402]  (hidden comment: Capacitor non-polarized)
C49  C: 10u  [0805]  (hidden comment: Capacitor non-polarized)
C50  C: 100n  [0402]  (hidden comment: Capacitor non-polarized)
C51  C: 100n  [0402]  (hidden comment: Capacitor non-polarized)
C52  C: 100n  [0402]  (hidden comment: Capacitor non-polarized)
C53  C: 100n  [0402]  (hidden comment: Capacitor non-polarized)
C56  C: 100n  [0402]  (hidden comment: Capacitor non-polarized)
C59  C: 10u  [0805]  (hidden comment: Capacitor non-polarized)
C62  C: 100n  [0402]  (hidden comment: Capacitor non-polarized)
C63  C: 100n  [0402]  (hidden comment: Capacitor non-polarized)
C75  C: 10u  [0805]  (hidden comment: Capacitor non-polarized)
C89  C: 4u7  [0603]  (hidden comment: Capacitor non-polarized)
C90  C: 4u7  [0603]  (hidden comment: Capacitor non-polarized)
C91  C: 10u  [0805]  (hidden comment: Capacitor non-polarized)
COL0  Test Pad  [PAD_1mm_SMD]  (value not drawn)  (no BOM)
COL1  Test Pad  [PAD_1mm_SMD]  (value not drawn)  (no BOM)
COL2  Test Pad  [PAD_1mm_SMD]  (value not drawn)  (no BOM)
COL3  Test Pad  [PAD_1mm_SMD]  (value not drawn)  (no BOM)
COL4  Test Pad  [PAD_1mm_SMD]  (value not drawn)  (no BOM)
COL5  Test Pad  [PAD_1mm_SMD]  (value not drawn)  (no BOM)
COL6  Test Pad  [PAD_1mm_SMD]  (value not drawn)  (no BOM)
COL7  Test Pad  [PAD_1mm_SMD]  (value not drawn)  (no BOM)
CS  Test Pad  [PAD_1mm_SMD]  (value not drawn)  (no BOM)
DM+  Test Pad  [PAD_1mm_SMD]  (value not drawn)  (no BOM)
DM-  Test Pad  [PAD_1mm_SMD]  (value not drawn)  (no BOM)
FLUSH  Test Pad  [PAD_1mm_SMD]  (value not drawn)  (no BOM)
FS  Test Pad  [PAD_1mm_SMD]  (value not drawn)  (no BOM)
GPO1  Test Pad  [PAD_1mm_SMD]  (value not drawn)  (no BOM)
GPO2  Test Pad  [PAD_1mm_SMD]  (value not drawn)  (no BOM)
GPO3  Test Pad  [PAD_1mm_SMD]  (value not drawn)  (no BOM)
L1  Z: 220R @ 100MHz  [0603]  (hidden comment: Ferrite)
L6  Z: 220R @ 100MHz  [0603]  (hidden comment: Ferrite)
L7  Z: 220R @ 100MHz  [0603]  (hidden comment: Ferrite)
L8  Z: 220R @ 100MHz  [0603]  (hidden comment: Ferrite)
L12  Z: 220R @ 100MHz  [0603]  (hidden comment: Ferrite)
LEN  Test Pad  [PAD_1mm_SMD]  (value not drawn)  (no BOM)
LH1  small optic  [lensholder_M12_CS_mult]  (value not drawn)  (no BOM)
LH2  NAME: NLS-2_171018  [lensholder_M12_NLS-2]  (hidden comment: small optic)
R3  R: 330R  [0603]  (hidden comment: Resistor)
R6  R: 10k  MountOption: DNP  [0402]  (hidden comment: Resistor)
R8  R: 330R  MountOption: DNP  [0603]  (hidden comment: Resistor)
R14  R: 10k  [0402]  (hidden comment: Resistor)
R17  R: 330R  [0603]  (hidden comment: Resistor)
R48  R: 10k  [0402]  (hidden comment: Resistor)
R54  R: 10k  [0402]  (hidden comment: Resistor)
R55  R: 10k  [0402]  (hidden comment: Resistor)
R56  R: 10k  [0402]  (hidden comment: Resistor)
ROW0  Test Pad  [PAD_1mm_SMD]  (value not drawn)  (no BOM)
ROW1  Test Pad  [PAD_1mm_SMD]  (value not drawn)  (no BOM)
ROW2  Test Pad  [PAD_1mm_SMD]  (value not drawn)  (no BOM)
ROW3  Test Pad  [PAD_1mm_SMD]  (value not drawn)  (no BOM)
ROW4  Test Pad  [PAD_1mm_SMD]  (value not drawn)  (no BOM)
ROW5  Test Pad  [PAD_1mm_SMD]  (value not drawn)  (no BOM)
ROW6  Test Pad  [PAD_1mm_SMD]  (value not drawn)  (no BOM)
ROW7  Test Pad  [PAD_1mm_SMD]  (value not drawn)  (no BOM)
RST  Test Pad  [PAD_1mm_SMD]  (value not drawn)  (no BOM)
SHUT  Test Pad  [PAD_1mm_SMD]  (value not drawn)  (no BOM)
U6  MLX75024  [COG-N44-MLX75023]  (parts A,B of 2)
U7  NAME: MLX75123RLA-BAG-000-RE  [ELP84-0.5-7-1]  (hidden comment: MLX75123xLA-BAG)  (parts A,B,C of 3)
V2  NAME: BSS138N  [SOT23-3-0.95-2.3]  (hidden comment: N-MOSFET)
V3  Schottky Diode  [SOD523]  (value not drawn)
V4  P-MOSFET  [SOT23-3-0.95-2.3]  (value not drawn)

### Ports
CCCLK (in), CSI (harness CSI), I2CL (harness I2C), LED.MOD_N (out), LED.MOD_P (out), SERIO3 (in)

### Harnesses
MLX: RST, COL[7..0], SHUT, PFLUSH, L_EN, DMIX_N, ROW[7..0], DMIX_P, CS
I2C: SCL, SDA
CSI: D[11..0], VSYNC, HSYNC, PCLK, QUIET, FSYNC, TRIGGER, nRESET

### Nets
1V8: L1.2 L6.1 L7.1 L8.1
1V8A: 1V8A.1 C12.2 C48.2 L7.2 U7.B14(VDDA_1V8)
1V8ADC: 1V8ADC.1 C47.2 C63.2 C91.2 L1.1 U7.A9(VDDA_ADC_1V8) U7.B5(VDDA_ADC_1V8)
1V8ADCS: 1V8ADCS.1 C45.2 C49.2 L8.2 U7.A10(VDDA_ADC_S_1V8)
1V8D: 1V8D.1 C2.1 C53.2 C59.2 C62.2 L6.2 U7.B12(VDD_I2C) U7.B20(VDDD_1V8) U7.B21(VDD_IO) U7.B30(VDD_IO) V3.1(A)
3V3: C11.2 C29.2 C32.2 C42.2 C52.2 C90.1 R6.1 R14.2 U6.23(VDDD) U6.33(VDDD) U6.44(VDDD) U7.B17(VDDT_3V3) V4.2(S)
3V3A: C30.2 C31.2 L12.2 U6.11(VDDA)
3V3A_CC: C46.2 C75.2 L12.1 U7.B4(VDDA_3V3)
3V3CC: 3V3CC.1 C50.1 C51.1 U7.A36(VDDD_3V3) U7.B38(VDDD_3V3) V3.2(K) V4.3(D)
ABIAS: ABIAS.1 C56.2 R3.2
GND: C2.2 C11.1 C12.1 C23.1 C29.1 C30.1 C31.1 C32.1 C34.1 C36.1 C37.1 C38.1 C42.1 C45.1 C46.1 C47.1 C48.1 C49.1 C50.2 C51.2 C52.1 C53.1 C56.1 C59.1 C62.1 C63.1 C75.1 C89.2 C90.2 C91.1 R48.2 R54.2 R55.2 R56.2 U6.0(EP) U6.12(AGND) U6.22(DGND) U6.32(DGND) U6.36(DGND) U6.39(DGND) U6.40(DGND) U6.43(DGND) U7.0(EP) U7.A5(GNDA_ADC_1V8) U7.A8(GND_IO) U7.A11(TEST[2]) U7.A16(GNDA_1V8) U7.A17(TEST[0]) U7.A18(GND_IO) U7.A22(GNDD_1V8) U7.A24(GND_IO) U7.A33(GND_IO) U7.A41(GND_IO) U7.B8(GNDA_ADC_1V8) U7.B9(GNDA_ADC_S_1V8) U7.B10(TEST[3]) U7.B15(GND_IO) U7.B16(TEST[1]) U7.B33(GND_IO) V2.2(S)
VMIX: C23.2 C34.2 C36.2 C37.2 C89.1 U6.37(MIXH) U6.38(MIXH) U6.41(MIXH) U6.42(MIXH)
CCCLK: U7.B13(CLK) ; port CCCLK
CSI.D0: U7.A30(PIXD[0])
CSI.D1: U7.B27(PIXD[1])
CSI.D2: U7.A29(PIXD[2])
CSI.D3: U7.B26(PIXD[3])
CSI.D4: U7.A28(PIXD[4])
CSI.D5: U7.B25(PIXD[5])
CSI.D6: U7.A27(PIXD[6])
CSI.D7: U7.B24(PIXD[7])
CSI.D8: U7.A26(PIXD[8])
CSI.D9: U7.B23(PIXD[9])
CSI.D10: U7.A25(PIXD[10])
CSI.D11: U7.B22(PIXD[11])
CSI.FSYNC: FS.1 U7.A31(FSYNC) ; port CSI.FSYNC
CSI.HSYNC: U7.B29(HSYNC) ; port CSI.HSYNC
CSI.nRESET: U7.A14(RSTB) ; port CSI.nRESET
CSI.PCLK: U7.B28(PIXCLK) ; port CSI.PCLK
CSI.QUIET: U7.A15(QUIET) ; port CSI.QUIET
CSI.TRIGGER: U7.A13(TRIGGER) ; port CSI.TRIGGER
CSI.VSYNC: U7.A32(VSYNC) ; port CSI.VSYNC
GPO0: R17.1 U7.B18(GPO_0)
GPO1: GPO1.1 U7.A20(GPO_1)
GPO2: GPO2.1 U7.B19(GPO_2)
GPO3: GPO3.1 U7.A21(GPO_3)
HPORB: U7.A19(HPORB) V2.1(G)
I2CL.SCL: U7.A12(SCL) ; port I2CL.SCL
I2CL.SDA: U7.B11(SDA) ; port I2CL.SDA
LED.MOD_N: U7.A34(LEDN) ; port LED.MOD_N
LED.MOD_P: U7.B31(LEDP) ; port LED.MOD_P
MLX.COL0: COL0.1 U6.24(COLUMN[0]) U7.B37(COL[0])
MLX.COL1: COL1.1 U6.25(COLUMN[1]) U7.A40(COL[1])
MLX.COL2: COL2.1 U6.26(COLUMN[2]) U7.B36(COL[2])
MLX.COL3: COL3.1 U6.27(COLUMN[3]) U7.A39(COL[3])
MLX.COL4: COL4.1 U6.28(COLUMN[4]) U7.B35(COL[4])
MLX.COL5: COL5.1 U6.29(COLUMN[5]) U7.A38(COL[5])
MLX.COL6: COL6.1 U6.30(COLUMN[6]) U7.B34(COL[6])
MLX.COL7: COL7.1 U6.31(COLUMN[7]) U7.A37(COL[7])
MLX.CS: CS.1 R6.2 R8.1 R17.2 R55.1 U6.21(CS) ; harness MLX.CS
MLX.DMIX_N: DM-.1 R54.1 U6.34(DMIX[1]) U7.B32(DMIX[1]) ; harness MLX.DMIX_N
MLX.DMIX_P: DM+.1 R48.1 U6.35(DMIX[0]) U7.A35(DMIX[0]) ; harness MLX.DMIX_P
MLX.L_EN: LEN.1 R56.1 U6.17(LATCH_ENABLE) U7.A4(LATCH_EN) ; harness MLX.L_EN
MLX.PFLUSH: FLUSH.1 U6.18(PIXELFLUSH) U7.B3(FLUSH) ; harness MLX.PFLUSH
MLX.ROW0: ROW0.1 U6.8(ROW[0]) U7.A42(ROW[0])
MLX.ROW1: ROW1.1 U6.7(ROW[1]) U7.B39(ROW[1])
MLX.ROW2: ROW2.1 U6.6(ROW[2]) U7.A43(ROW[2])
MLX.ROW3: ROW3.1 U6.5(ROW[3]) U7.B40(ROW[3])
MLX.ROW4: ROW4.1 U6.4(ROW[4]) U7.A44(ROW[4])
MLX.ROW5: ROW5.1 U6.3(ROW[5]) U7.A1(ROW[5])
MLX.ROW6: ROW6.1 U6.2(ROW[6]) U7.B1(ROW[6])
MLX.ROW7: ROW7.1 U6.1(ROW[7]) U7.A2(ROW[7])
MLX.RST: RST.1 U6.19(CORE_RESET) U7.A3(ARRAY_RST) ; harness MLX.RST
MLX.SHUT: SHUT.1 U6.20(SHUTTER) U7.B2(SHUT) ; harness MLX.SHUT
OUT0: U6.15(OUT0) U7.B6(A_IN[0])
OUT1: U6.16(OUT1) U7.A6(A_IN[1])
OUT2: U6.14(OUT2) U7.A7(A_IN[2])
OUT3: U6.13(OUT3) U7.B7(A_IN[3])
SERIO3: R8.2 ; port SERIO3
NetC38_2: C38.2 U6.10(PIXELVDD)
NetR3_1: R3.1 U6.9(ARRAYBIAS)
NetR14_1: R14.1 V2.3(D) V4.1(G)

Not connected (* = marked no-connect by the designer): LH2 1 2; U7 A23(n.c.)

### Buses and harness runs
bus CSI.D[11..0]
bus MLX.COL[7..0]
bus MLX.ROW[7..0]
bus OUT[3..0]
harness CSI = port CSI
harness I2CL = port I2CL

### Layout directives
net class <Hi-Speed>: LED.MOD_N, LED.MOD_P, MLX.CS, MLX.DMIX_N, MLX.DMIX_P
differential pair; net class DIFF100: LED.MOD_N, LED.MOD_P, MLX.CS, MLX.DMIX_N, MLX.DMIX_P
net class <Power>: 1V8A, 1V8ADC, 1V8ADCS, 1V8D, 3V3CC, ABIAS

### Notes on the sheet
- ToF Sensor
- ToF-CC

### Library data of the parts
1V8A 1V8ADC 1V8ADCS 1V8D 3V3CC COL0-COL7 CS DM+ DM- FLUSH FS GPO1-GPO3 LEN ROW0-ROW7 RST SHUT = D58E77CC-74E0-4972-9B60-0D1F1EE06ED8: Test Pad 1mm; Manufacturer: Bluetechnix; ArticleNumber: 810-0021; Inventory Storage Name: L2; Sachgruppe: SV_TEST; IsReviewed: 1; Montage: THD
ABIAS = 27F6ED3A-68E1-4461-ACCB-196987D0D511: as 1V8 on sheet Power
C2 C11 C31 C32 C34 C36 C42 C45-C48 C50-C53 C56 C62 C63 = 54C877D5-E705-4C14-AD3D-8F4F7B57D597: C-0402-100n-16V-10%; Manufacturer: Murata; ArticleNumber: 710-0138; NAME: GRM155R71C104KA88D; Inventory Storage Name: LBaut; Inventory Storage Section: C3; Sachgruppe: C_KERAMIK; SachgruppeCode: Keramikscheiben; IsReviewed: 1; U: 16V; Toleranz: 10%; Dielektrikum: X7R; T_Koeffizient: ± 15%; T-bereich: -55°C : +125°C; Montage: SMD; InternalPrice: 0,009756; InternalStock: 539102
C12 C29 C30 C37 C49 C59 C75 C91 = D0FA8253-90B1-4ECC-BCBB-ABE84B083618: C-0805-10u-6.3V-X7R; Manufacturer: Murata; ArticleNumber: 710-0157; NAME: MC0805B106K6R3CT; Inventory Storage Name: LBaut; Inventory Storage Section: C3; Sachgruppe: C_KERAMIK; SachgruppeCode: Keramikscheiben; IsReviewed: 1; InternalPrice: 0,27054; InternalStock: 620; U: 6.3V; Toleranz: 10%; Dielektrikum: X7R; T_Koeffizient: ± 15%; T-bereich: -55°C : +125°C; Montage: SMD
C23 = 85fb7b5b-9611-43b8-8d58-2b78e382f91e: C-1206-100u-6.3V-20%-X6T; Manufacturer: Murata; ArticleNumber: 710-0330; NAME: GRM31CD80J107ME39L; Inventory Storage Name: LBaut; Inventory Storage Section: C7; Sachgruppe: C_KERAMIK; SachgruppeCode: Keramikscheiben; IsReviewed: 1; InternalPrice: 0,428837; InternalStock: 44; U: 6.3V; Toleranz: 20%; Dielektrikum: X6T; T_Koeffizient: ± 15%; T-bereich: -55°C : +105°C; Montage: SMD
C38 = 98DACC71-806A-4FEE-A07A-D9A6BAB2B1B9: C-0402-1u-6.3V-20%; Manufacturer: Taiyo Yuden; ArticleNumber: 710-0170; NAME: GRM155R70J105MA12D; Inventory Storage Name: LBaut; Inventory Storage Section: C4; Sachgruppe: C_KERAMIK; SachgruppeCode: Keramikscheiben; IsReviewed: 1; InternalPrice: 0,018461; InternalStock: 500; U: 6.3V; Toleranz: 20%; Dielektrikum: X7R; T-bereich: -55°C : +125°C; Montage: SMD
C89 C90 = E75EC942-B97D-4F35-9B30-0E69ABA45798: C-0603-4u7-6.3V-10%; Manufacturer: Kemet; ArticleNumber: 710-0008; NAME: C0603C475K9PAC; Inventory Storage Name: LBaut; Inventory Storage Section: CR1; Sachgruppe: C_KERAMIK; SachgruppeCode: Keramikscheiben; IsReviewed: 1; InternalPrice: 0,00975; InternalStock: 19132; U: 6.3V; Toleranz: 10%; Dielektrikum: X5R; T_Koeffizient: ± 15%; T-bereich: -55°C : +85°C; Montage: SMD
L1 L6-L8 L12 = 07176BF7-A3FD-44A1-A821-88F0A6433C5F: F-0603-220Z-500mA; Manufacturer: Würth Elektronik; ArticleNumber: 770-0061; NAME: 74279263; Inventory Storage Name: LBaut; Inventory Storage Section: I5; Sachgruppe: FI_FERRITPERLEN; SachgruppeCode: Ferritperlen; IsReviewed: 1; InternalPrice: 0,051181; InternalStock: 326; R_dc: 0R3; Bandbreite: 190R @ 2GHz; Frequenz: 400MHz; I_max: 500mA; Montage: SMD; T-bereich: -55°C : +125°C
LH1 = fb9d6639-ec39-4f27-9db3-01e0c5ccb563: Lense Holder M12, CS, multiple; Manufacturer: Unbranded; ArticleNumber: 880-0182; Inventory Storage Name: L2; Sachgruppe: MNT_ZUBEHOER; SachgruppeCode: Zubehör; IsReviewed: 1; Groesse: M12, CS; Montage: versch.
LH2 = 6a91d241-ddc7-433f-aaf5-84eaeffba76b: Lens Holder for M12 lense 3.75mm high; Manufacturer: Naotech; ArticleNumber: 880-0244; Inventory Storage Name: L2; Sachgruppe: MNT_ZUBEHOER; SachgruppeCode: Zubehör; IsReviewed: 1; InternalPrice: 0; InternalStock: 66; Gegenstueck: M12 Linse; Groesse: 22x18x3.75; Montage: M2; Kommentar: 18mm screw-distance; T-bereich: Alu
R3 R8 R17 = A3495A76-5718-4BF3-84D0-31FEB97D37C9: R-0603-330R-1%; Manufacturer: Multicomp; ArticleNumber: 780-0068; NAME: MC 0.0654W 0603 1% 330R; Inventory Storage Name: LBaut; Inventory Storage Section: R2; Sachgruppe: R_DICKSCHICHT; SachgruppeCode: Dickschicht; IsReviewed: 1; InternalPrice: 0,012307; InternalStock: 112; P: 0.063W; Toleranz: 1%; T_Koeffizient: ± 100ppm/°C; Montage: SMD
R6 R14 R48 R54-R56 = BCCEBF77-39D2-4523-BB97-913D11062098: as R10 on sheet Power
U6 = 2041fcf8-dfaf-4804-8ae0-af23c2aad8e4: QVGA 3D ToF Sensor; Manufacturer: Melexis; ArticleNumber: 730-0280; Inventory Storage Name: LBaut; Inventory Storage Section: V20; Sachgruppe: SENSOREN; IsReviewed: 1; InternalPrice: 0; InternalStock: 6; Typ: CMOS 3D Sensor; Interface: analog; Messgroesse: 1/3 inch (4:3); Messbereich: 80k; U: 3.0V : 3.6V; T-bereich: -40°C : +105°C; Bauform: COG-44; Montage: SMD
U7 = 18af0085-4cb3-4911-96c3-c6148f48ab61: ToF Companion Chip for MLX7502x Rev.B; Manufacturer: Melexis; ArticleNumber: 700-1160; Inventory Storage Name: L2; Sachgruppe: IC_SPEZIAL; SachgruppeCode: Spezial Funktionen; IsReviewed: 0; Typ: ToF-CC; U: 1.8V, 3.3V; T-bereich: -40°C : 105°C; Bauform: LPC84; Montage: SMD; Kommentar: ToF-Controller for MLX75023
V2 = 03C5F5B7-A326-4CDC-AFAF-8F2D2E9943FF: BSS138; Manufacturer: Infineon; ArticleNumber: 720-0038; Inventory Storage Name: LBaut; Inventory Storage Section: T4; Sachgruppe: SE_FET; SachgruppeCode: FET; IsReviewed: 1; InternalPrice: 0,025428; InternalStock: 21924; R_dson: 3.5R; U_ds: 60V; I_d: 230mA; U_gs(max): 20V; U_gs(nom): 0.6V : 1.4V; P: 360mW; Bauform: SOT-23; Montage: SMD; T-bereich: -55°C : +150°C
V3 = FC861B13-3265-48F1-9078-83CD9385FA64: PMEG2010AEB; Manufacturer: NXP; ArticleNumber: 730-0086; Inventory Storage Name: LBaut; Inventory Storage Section: V7; Sachgruppe: SE_SCHOTTKY; IsReviewed: 1; InternalPrice: 0,104827; InternalStock: 24676; U_f: 620mV; U_r: 20V; I_f(nenn): 1A; I_f(max): 6A; I_r: 1.5mA; Bauform: SOD-523; Montage: SMD; T-bereich: -65°C : +150°C
V4 = 5BB558C5-1CEB-4DBB-9635-955197B79569: IRLML6401PBF; Manufacturer: International Rectifier; ArticleNumber: 720-0040; Inventory Storage Name: LBaut; Inventory Storage Section: T4; Inventory Storage Info: 10851; Sachgruppe: SE_FET; SachgruppeCode: FET; IsReviewed: 1; InternalPrice: 0,287692; InternalStock: 90; R_dson: 50mR; U_ds: -12V; I_d: 4.3A; U_gs(max): -0.95V; U_gs(nom): -0.55V; P: 1.3W; Bauform: SOT-23; Montage: SMD; T-bereich: -55°C : +150°C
